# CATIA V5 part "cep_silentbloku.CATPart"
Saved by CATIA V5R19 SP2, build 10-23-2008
Part number: cep_silentbloku
Bounding box of the stored display mesh (mm): x -34.99 to 34.99, y -85 to 85, z -34.885 to 34.885
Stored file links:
  C:\Users\Martiin\Desktop\9.semestr\Projekt-diplomka\3D model\silentbloky\cep_silentbloku.CATPart
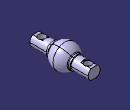
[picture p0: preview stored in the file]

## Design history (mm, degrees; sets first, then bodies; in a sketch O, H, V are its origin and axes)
Body1 (main body)
  Sketch1 on yz-plane, origin (0, 0, 0), H (0, 1, 0), V (0, 0, 1)
    arc A1 centre (0, 0) radius 35 from (0, 35) to (-27.8609, 21.1842) ccw
    point P1 (-35, 20)
    line L1 (-35, 20) -> (-30.249, 20)
    line L2 (-35, 0) -> (-35, 20)
    arc A2 centre (-30.249, 23) radius 3 from (-27.8609, 21.1842) to (-30.249, 20) cw
    point P2 (-27.8609, 21.1842)
    point P3 (-30.249, 20)
    construction line L3 (0, 43.9251) -> (0, -30.2246)
    point P5 (0, 43.9251)
    construction line L4 (-44.9387, 0) -> (49.0391, 0)
    point P7 (-44.9387, 0)
    point P9 (-35, 0)
    point P10 (0, 35)
    construction line L5 through (0, 0) direction (0, 1)
    point P14 (35, 20)
    point P15 (27.8609, 21.1842)
    point P16 (30.249, 20)
    point P18 (44.9387, 0)
    point P19 (35, 0)
    point P20 (0, 35)
    arc A3 centre (0, 0) radius 35 from (0, 35) to (27.8609, 21.1842) cw
    line L6 (35, 20) -> (30.249, 20)
    line L7 (35, 0) -> (35, 20)
    arc A4 centre (30.249, 23) radius 3 from (27.8609, 21.1842) to (30.249, 20) ccw
    axis line L8 (-50.4914, 0) -> (55.8491, 0)
    radius A1 = 35
    distance H L1 = 20
    distance V L2 = 35
    radius A2 = 3
    horizontal: L1 H, L4 H, L8 H
    vertical: L2 V, L3 V
    tangency: A2 A1, A2 L1
    coincidence: P5 V, P7 H, L4 P9, L3 P10, P10 P20
    symmetry: V L5 L3, P1 P14 L3, P2 P15 L3, P3 P16 L3, P7 P18 L3, P9 P19 L3, P10 P20 L3, A1 A3 L3, L1 L6 L3, L2 L7 L3, A2 A4 L3
  Shaft1: profile Sketch1, axis Sketch1.L8, angle 360
  Sketch2 on face of Shaft1 from Sketch1.L7, origin (0, 35, 0), H (-1, 0, 0), V (0, 0, 1)
    circle A1 centre (0, 0) radius 17.5
    point P1 (0, 17.5)
    radius A1 = 17.5
    coincidence: A1 P1, P1 V
  Pad1: profile Sketch2, direction (0, 1, 0), length 50
  Sketch3 on end face of Pad1, origin (0, 85, 0), H (-1, 0, 0), V (0, 0, 1)
    line L1 (-9.0139, 15) -> (9.0139, 15)
    arc A1 centre (0, 0) radius 17.5 from (9.0139, 15) to (-9.0139, 15) ccw
    point P1 (-9.0139, 15)
    point P2 (9.0139, 15)
    construction line L2 (6.0834, 0) -> (36.3656, 0)
    point P3 (6.0834, 0)
    point P5 (-9.0139, -15)
    point P6 (9.0139, -15)
    line L3 (-9.0139, -15) -> (9.0139, -15)
    arc A2 centre (0, 0) radius 17.5 from (9.0139, -15) to (-9.0139, -15) cw
    radius A1 = 17.5
    distance H L1 = 15
    horizontal: L1 H, L2 H
    coincidence: P3 H
    symmetry: P1 P5 L2, P2 P6 L2, L1 L3 L2, A1 A2 L2
  Pocket1: profile Sketch3, direction (0, -1, 0), length 30
  Sketch4 on face of Pocket1 from Sketch3.L1, origin (0, 0, 15), H (1, 0, 0), V (0, 1, 0)
    point P1 (0, 67.5)
    reference projected line E1 (9.0139, 85) -> (-9.0139, 85) from edge [end face of Pad1 | face of Pocket1 from Sketch3.L1]
    distance P1 E1 = 17.5
    coincidence: P1 V
  Sketch5 on face of Pocket1 from Sketch3.L1, origin (0, 67.5, 15), H (1, 0, 0), V (0, 1, 0)
    point P1 (0, 0)
    reference projected line E1 (-35, -67.5) -> (35, -67.5) from edge [face of Shaft1 from Sketch1.A1 | face of Shaft1 from Sketch1.A3]
    distance P1 E1 = 67.5
  Hole1: placed by Sketch5, at (0, 67.5, 15) direction (0, 0, -1), diameter 21, through (limit type 6)
  Mirror1: of Pad1, Pocket1, Hole1, about zx-plane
